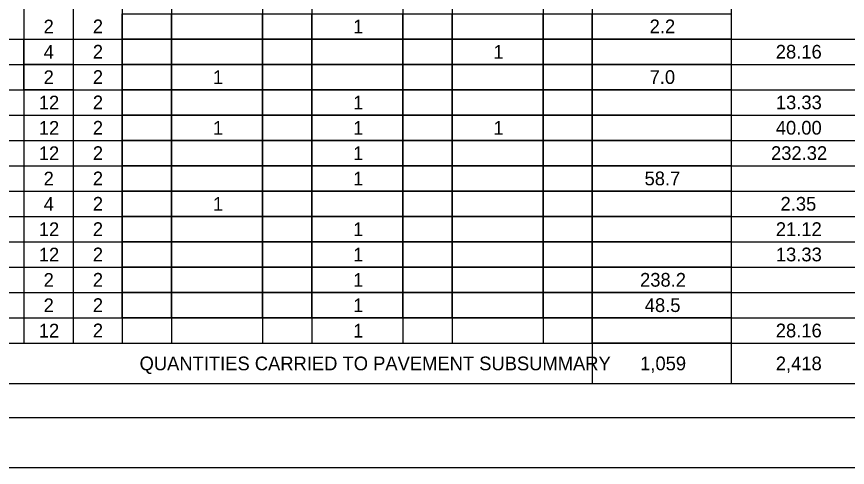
# Model space of a CAD drawing. Extents: x 0 to 34, y 0 to 22.
# Drawn here: x 8.44 to 16.79, y 0 to 4.54 of the extents above; entities that cross this region are included whole.
import ezdxf

# ---------------------------------------------------------------- set-up
doc = ezdxf.new("R2010")
doc.units = 0
for name, color, linetype in [('Default', 7, 'Continuous'), ('SH_Border', 7, 'Continuous'), ('SH_Cut_Line', 7, 'Continuous')]:
    doc.layers.add(name, color=color, linetype=linetype)

msp = doc.modelspace()

# ---------------------------------------------------------------- linework, layer by layer
at = {"layer": 'Default'}
for p, q in [((14.2264, 21.4685), (14.2264, 0.8435)), ((15.6214, 21.4685), (15.6214, 0.8435)), ((8.5114, 21.2135), (8.5114, 1.2485)), ((9.0064, 21.2135), (9.0064, 1.2485)), ((9.5014, 21.2135), (9.5014, 1.2485)), ((9.9964, 18.9335), (9.9964, 1.2485)), ((10.9114, 18.9335), (10.9114, 1.2485)), ((11.4064, 18.9335), (11.4064, 1.2485)), ((12.3214, 18.9335), (12.3214, 1.2485)), ((12.8164, 18.9335), (12.8164, 1.2485)), ((13.7314, 18.9335), (13.7314, 1.2485)), ((4.7014, 4.3085), (28.7614, 4.3085)), ((4.7014, 4.0535), (28.7614, 4.0535)), ((4.7014, 3.7985), (28.7614, 3.7985)), ((4.7014, 3.5435), (28.7614, 3.5435)), ((4.7014, 3.2885), (28.7614, 3.2885)), ((4.7014, 3.0335), (28.7614, 3.0335)), ((4.7014, 2.7785), (28.7614, 2.7785)), ((4.7014, 2.5235), (28.7614, 2.5235)), ((4.7014, 2.2685), (28.7614, 2.2685)), ((4.7014, 2.0135), (28.7614, 2.0135)), ((4.7014, 1.7585), (28.7614, 1.7585)), ((4.7014, 1.5035), (28.7614, 1.5035)), ((4.7014, 1.2485), (28.7614, 1.2485)), ((4.7014, 0.8435), (28.7614, 0.8435))]:
    msp.add_line(p, q, dxfattribs=at)
for points in [[(9.5014, 4.5635), (9.9964, 4.5635), (9.9964, 4.3085), (9.5014, 4.3085)], [(9.9964, 4.5635), (10.9114, 4.5635), (10.9114, 4.3085), (9.9964, 4.3085)], [(10.9114, 4.5635), (11.4064, 4.5635), (11.4064, 4.3085), (10.9114, 4.3085)], [(11.4064, 4.5635), (12.3214, 4.5635), (12.3214, 4.3085), (11.4064, 4.3085)], [(12.3214, 4.5635), (12.8164, 4.5635), (12.8164, 4.3085), (12.3214, 4.3085)], [(12.8164, 4.5635), (13.7314, 4.5635), (13.7314, 4.3085), (12.8164, 4.3085)], [(13.7314, 4.5635), (14.2264, 4.5635), (14.2264, 4.3085), (13.7314, 4.3085)], [(14.2264, 4.5635), (15.6214, 4.5635), (15.6214, 4.3085), (14.2264, 4.3085)], [(8.5114, 4.3085), (9.0064, 4.3085), (9.0064, 4.0535), (8.5114, 4.0535)], [(9.5014, 4.3085), (9.9964, 4.3085), (9.9964, 4.0535), (9.5014, 4.0535)], [(9.9964, 4.3085), (10.9114, 4.3085), (10.9114, 4.0535), (9.9964, 4.0535)], [(10.9114, 4.3085), (11.4064, 4.3085), (11.4064, 4.0535), (10.9114, 4.0535)], [(11.4064, 4.3085), (12.3214, 4.3085), (12.3214, 4.0535), (11.4064, 4.0535)], [(12.3214, 4.3085), (12.8164, 4.3085), (12.8164, 4.0535), (12.3214, 4.0535)], [(12.8164, 4.3085), (13.7314, 4.3085), (13.7314, 4.0535), (12.8164, 4.0535)], [(13.7314, 4.3085), (14.2264, 4.3085), (14.2264, 4.0535), (13.7314, 4.0535)], [(14.2264, 4.3085), (15.6214, 4.3085), (15.6214, 4.0535), (14.2264, 4.0535)], [(8.5114, 4.0535), (9.0064, 4.0535), (9.0064, 3.7985), (8.5114, 3.7985)], [(9.5014, 4.0535), (9.9964, 4.0535), (9.9964, 3.7985), (9.5014, 3.7985)], [(9.9964, 4.0535), (10.9114, 4.0535), (10.9114, 3.7985), (9.9964, 3.7985)], [(10.9114, 4.0535), (11.4064, 4.0535), (11.4064, 3.7985), (10.9114, 3.7985)], [(11.4064, 4.0535), (12.3214, 4.0535), (12.3214, 3.7985), (11.4064, 3.7985)], [(12.3214, 4.0535), (12.8164, 4.0535), (12.8164, 3.7985), (12.3214, 3.7985)], [(12.8164, 4.0535), (13.7314, 4.0535), (13.7314, 3.7985), (12.8164, 3.7985)], [(13.7314, 4.0535), (14.2264, 4.0535), (14.2264, 3.7985), (13.7314, 3.7985)], [(14.2264, 4.0535), (15.6214, 4.0535), (15.6214, 3.7985), (14.2264, 3.7985)], [(9.5014, 3.7985), (9.9964, 3.7985), (9.9964, 3.5435), (9.5014, 3.5435)], [(9.9964, 3.7985), (10.9114, 3.7985), (10.9114, 3.5435), (9.9964, 3.5435)], [(10.9114, 3.7985), (11.4064, 3.7985), (11.4064, 3.5435), (10.9114, 3.5435)], [(11.4064, 3.7985), (12.3214, 3.7985), (12.3214, 3.5435), (11.4064, 3.5435)], [(12.3214, 3.7985), (12.8164, 3.7985), (12.8164, 3.5435), (12.3214, 3.5435)], [(12.8164, 3.7985), (13.7314, 3.7985), (13.7314, 3.5435), (12.8164, 3.5435)], [(13.7314, 3.7985), (14.2264, 3.7985), (14.2264, 3.5435), (13.7314, 3.5435)], [(14.2264, 3.7985), (15.6214, 3.7985), (15.6214, 3.5435), (14.2264, 3.5435)], [(9.5014, 3.5435), (9.9964, 3.5435), (9.9964, 3.2885), (9.5014, 3.2885)], [(9.9964, 3.5435), (10.9114, 3.5435), (10.9114, 3.2885), (9.9964, 3.2885)], [(10.9114, 3.5435), (11.4064, 3.5435), (11.4064, 3.2885), (10.9114, 3.2885)], [(11.4064, 3.5435), (12.3214, 3.5435), (12.3214, 3.2885), (11.4064, 3.2885)], [(12.3214, 3.5435), (12.8164, 3.5435), (12.8164, 3.2885), (12.3214, 3.2885)], [(12.8164, 3.5435), (13.7314, 3.5435), (13.7314, 3.2885), (12.8164, 3.2885)], [(13.7314, 3.5435), (14.2264, 3.5435), (14.2264, 3.2885), (13.7314, 3.2885)], [(14.2264, 3.5435), (15.6214, 3.5435), (15.6214, 3.2885), (14.2264, 3.2885)], [(9.5014, 3.2885), (9.9964, 3.2885), (9.9964, 3.0335), (9.5014, 3.0335)], [(9.9964, 3.2885), (10.9114, 3.2885), (10.9114, 3.0335), (9.9964, 3.0335)], [(10.9114, 3.2885), (11.4064, 3.2885), (11.4064, 3.0335), (10.9114, 3.0335)], [(11.4064, 3.2885), (12.3214, 3.2885), (12.3214, 3.0335), (11.4064, 3.0335)], [(12.3214, 3.2885), (12.8164, 3.2885), (12.8164, 3.0335), (12.3214, 3.0335)], [(12.8164, 3.2885), (13.7314, 3.2885), (13.7314, 3.0335), (12.8164, 3.0335)], [(13.7314, 3.2885), (14.2264, 3.2885), (14.2264, 3.0335), (13.7314, 3.0335)], [(14.2264, 3.2885), (15.6214, 3.2885), (15.6214, 3.0335), (14.2264, 3.0335)], [(9.5014, 3.0335), (9.9964, 3.0335), (9.9964, 2.7785), (9.5014, 2.7785)], [(9.9964, 3.0335), (10.9114, 3.0335), (10.9114, 2.7785), (9.9964, 2.7785)], [(10.9114, 3.0335), (11.4064, 3.0335), (11.4064, 2.7785), (10.9114, 2.7785)], [(11.4064, 3.0335), (12.3214, 3.0335), (12.3214, 2.7785), (11.4064, 2.7785)], [(12.3214, 3.0335), (12.8164, 3.0335), (12.8164, 2.7785), (12.3214, 2.7785)], [(12.8164, 3.0335), (13.7314, 3.0335), (13.7314, 2.7785), (12.8164, 2.7785)], [(13.7314, 3.0335), (14.2264, 3.0335), (14.2264, 2.7785), (13.7314, 2.7785)], [(14.2264, 3.0335), (15.6214, 3.0335), (15.6214, 2.7785), (14.2264, 2.7785)], [(9.5014, 2.7785), (9.9964, 2.7785), (9.9964, 2.5235), (9.5014, 2.5235)], [(9.9964, 2.7785), (10.9114, 2.7785), (10.9114, 2.5235), (9.9964, 2.5235)], [(10.9114, 2.7785), (11.4064, 2.7785), (11.4064, 2.5235), (10.9114, 2.5235)], [(11.4064, 2.7785), (12.3214, 2.7785), (12.3214, 2.5235), (11.4064, 2.5235)], [(12.3214, 2.7785), (12.8164, 2.7785), (12.8164, 2.5235), (12.3214, 2.5235)], [(12.8164, 2.7785), (13.7314, 2.7785), (13.7314, 2.5235), (12.8164, 2.5235)], [(13.7314, 2.7785), (14.2264, 2.7785), (14.2264, 2.5235), (13.7314, 2.5235)], [(14.2264, 2.7785), (15.6214, 2.7785), (15.6214, 2.5235), (14.2264, 2.5235)], [(9.5014, 2.5235), (9.9964, 2.5235), (9.9964, 2.2685), (9.5014, 2.2685)], [(9.9964, 2.5235), (10.9114, 2.5235), (10.9114, 2.2685), (9.9964, 2.2685)], [(10.9114, 2.5235), (11.4064, 2.5235), (11.4064, 2.2685), (10.9114, 2.2685)], [(11.4064, 2.5235), (12.3214, 2.5235), (12.3214, 2.2685), (11.4064, 2.2685)], [(12.3214, 2.5235), (12.8164, 2.5235), (12.8164, 2.2685), (12.3214, 2.2685)], [(12.8164, 2.5235), (13.7314, 2.5235), (13.7314, 2.2685), (12.8164, 2.2685)], [(13.7314, 2.5235), (14.2264, 2.5235), (14.2264, 2.2685), (13.7314, 2.2685)], [(14.2264, 2.5235), (15.6214, 2.5235), (15.6214, 2.2685), (14.2264, 2.2685)], [(9.5014, 2.2685), (9.9964, 2.2685), (9.9964, 2.0135), (9.5014, 2.0135)], [(9.9964, 2.2685), (10.9114, 2.2685), (10.9114, 2.0135), (9.9964, 2.0135)], [(10.9114, 2.2685), (11.4064, 2.2685), (11.4064, 2.0135), (10.9114, 2.0135)], [(11.4064, 2.2685), (12.3214, 2.2685), (12.3214, 2.0135), (11.4064, 2.0135)], [(12.3214, 2.2685), (12.8164, 2.2685), (12.8164, 2.0135), (12.3214, 2.0135)], [(12.8164, 2.2685), (13.7314, 2.2685), (13.7314, 2.0135), (12.8164, 2.0135)], [(13.7314, 2.2685), (14.2264, 2.2685), (14.2264, 2.0135), (13.7314, 2.0135)], [(14.2264, 2.2685), (15.6214, 2.2685), (15.6214, 2.0135), (14.2264, 2.0135)], [(9.5014, 2.0135), (9.9964, 2.0135), (9.9964, 1.7585), (9.5014, 1.7585)], [(9.9964, 2.0135), (10.9114, 2.0135), (10.9114, 1.7585), (9.9964, 1.7585)], [(10.9114, 2.0135), (11.4064, 2.0135), (11.4064, 1.7585), (10.9114, 1.7585)], [(11.4064, 2.0135), (12.3214, 2.0135), (12.3214, 1.7585), (11.4064, 1.7585)], [(12.3214, 2.0135), (12.8164, 2.0135), (12.8164, 1.7585), (12.3214, 1.7585)], [(12.8164, 2.0135), (13.7314, 2.0135), (13.7314, 1.7585), (12.8164, 1.7585)], [(13.7314, 2.0135), (14.2264, 2.0135), (14.2264, 1.7585), (13.7314, 1.7585)], [(14.2264, 2.0135), (15.6214, 2.0135), (15.6214, 1.7585), (14.2264, 1.7585)], [(9.5014, 1.7585), (9.9964, 1.7585), (9.9964, 1.5035), (9.5014, 1.5035)], [(9.9964, 1.7585), (10.9114, 1.7585), (10.9114, 1.5035), (9.9964, 1.5035)], [(10.9114, 1.7585), (11.4064, 1.7585), (11.4064, 1.5035), (10.9114, 1.5035)], [(11.4064, 1.7585), (12.3214, 1.7585), (12.3214, 1.5035), (11.4064, 1.5035)], [(12.3214, 1.7585), (12.8164, 1.7585), (12.8164, 1.5035), (12.3214, 1.5035)], [(12.8164, 1.7585), (13.7314, 1.7585), (13.7314, 1.5035), (12.8164, 1.5035)], [(13.7314, 1.7585), (14.2264, 1.7585), (14.2264, 1.5035), (13.7314, 1.5035)], [(14.2264, 1.7585), (15.6214, 1.7585), (15.6214, 1.5035), (14.2264, 1.5035)], [(14.2264, 1.5035), (15.6214, 1.5035), (15.6214, 1.2485), (14.2264, 1.2485)]]:
    msp.add_lwpolyline(points, close=True, dxfattribs=at)
at = {"layer": 'SH_Border'}
msp.add_lwpolyline([(1.5, 21.5), (33.5, 21.5), (33.5, 0.5), (1.5, 0.5)], close=True, dxfattribs=at)
at = {"layer": 'SH_Cut_Line'}
msp.add_lwpolyline([(0, 0), (34, 0), (34, 22), (0, 22)], close=True, dxfattribs=at)

# ---------------------------------------------------------------- texts
at = {"layer": 'Default'}
for s, p in [('2', (8.7102, 4.367)), ('2', (9.2052, 4.3685)), ('1', (11.8224, 4.367)), ('2.2', (14.8028, 4.3685)), ('4', (8.7117, 4.112)), ('2', (9.2052, 4.1135)), ('1', (13.2324, 4.112)), ('28.16', (16.0709, 4.1135)), ('2', (8.7102, 3.857)), ('2', (9.2052, 3.8585)), ('1', (10.4124, 3.857)), ('7.0', (14.8025, 3.8585)), ('12', (8.6619, 3.602)), ('2', (9.2052, 3.6035)), ('1', (11.8224, 3.602)), ('13.33', (16.0718, 3.6035)), ('12', (8.6619, 3.347)), ('2', (9.2052, 3.3485)), ('1', (10.4124, 3.347)), ('1', (11.8224, 3.347)), ('1', (13.2324, 3.347)), ('40.00', (16.0711, 3.3485)), ('12', (8.6619, 3.092)), ('2', (9.2052, 3.0935)), ('1', (11.8224, 3.092)), ('232.32', (16.0231, 3.0935)), ('2', (8.7102, 2.837)), ('2', (9.2052, 2.8385)), ('1', (11.8224, 2.837)), ('58.7', (14.7517, 2.8385)), ('4', (8.7117, 2.582)), ('2', (9.2052, 2.5835)), ('1', (10.4124, 2.582)), ('2.35', (16.1187, 2.5835)), ('12', (8.6619, 2.327)), ('2', (9.2052, 2.3285)), ('1', (11.8224, 2.327)), ('21.12', (16.0714, 2.3285)), ('12', (8.6619, 2.072)), ('2', (9.2052, 2.0735)), ('1', (11.8224, 2.072)), ('13.33', (16.0718, 2.0735)), ('2', (8.7102, 1.817)), ('2', (9.2052, 1.8185)), ('1', (11.8224, 1.817)), ('238.2', (14.7064, 1.8185)), ('2', (8.7102, 1.562)), ('2', (9.2052, 1.5635)), ('1', (11.8224, 1.562)), ('48.5', (14.7537, 1.5635)), ('12', (8.6619, 1.307)), ('2', (9.2052, 1.3085)), ('1', (11.8224, 1.307)), ('28.16', (16.0709, 1.3085)), ('QUANTITIES CARRIED TO PAVEMENT SUBSUMMARY', (9.6751, 0.977)), ('1,059', (14.7073, 0.977)), ('2,418', (16.0712, 0.977))]:
    msp.add_text(s, height=0.138, dxfattribs=at).set_placement(p)

doc.saveas('drawing.dxf')
